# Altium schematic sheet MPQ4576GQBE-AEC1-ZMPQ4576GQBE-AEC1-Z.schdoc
size 127 x 101 mm
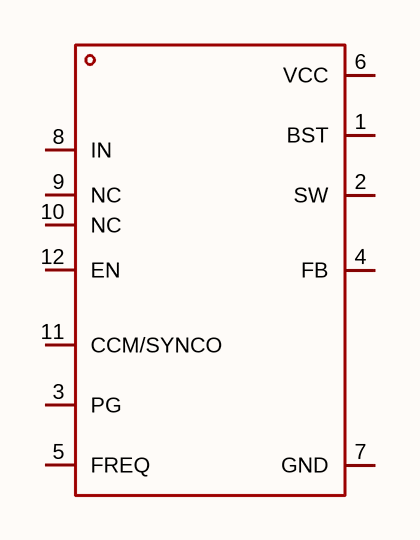
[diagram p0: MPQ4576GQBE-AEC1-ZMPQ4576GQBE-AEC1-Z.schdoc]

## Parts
U?  mpq4576gqbe-aec1-z  [QFN-12_L3.0-W2.5-P0.5_MPQ4572]  (value not drawn)

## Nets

Not connected (* = marked no-connect by the designer): U? 1(BST) 2(SW) 3(PG) 4(FB) 5(FREQ) 6(VCC) 7(GND) 8(IN) 9(NC) 10(NC) 11(CCM/SYNCO) 12(EN)

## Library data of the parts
U? = mpq4576gqbe-aec1-z: 功能类型:降压型;工作电压:4.5V~60V;输出电压:1V~54V;输出电流:600mA;输出类型:可调;; Manufacturer: MPS(芯源); AddInBom: yes; Function: 降压型; Output Voltage: 1V~54V; Output Current: 600mA; Frequency - Switching: 400kHz; Synchronous Rectifier: 是; Number of Outputs: 1; Topology: 降压式; Quiescent Current: 40uA; Switch tube (built-in/external): 内置; Output Type: 可调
